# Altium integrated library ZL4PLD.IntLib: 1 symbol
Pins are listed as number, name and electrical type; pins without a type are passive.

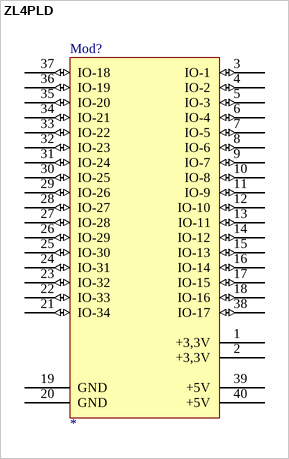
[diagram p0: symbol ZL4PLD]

## ZL4PLD
designator Mod?
www.btc.pl
footprint ZL4PLD
pins: 1 +3,3V (power), 2 +3,3V (power), 3 IO-1 (io), 4 IO-2 (io), 5 IO-3 (io), 6 IO-4 (io), 7 IO-5 (io), 8 IO-6 (io), 9 IO-7 (io), 10 IO-8 (io), 11 IO-9 (io), 12 IO-10 (io), 13 IO-11 (io), 14 IO-12 (io), 15 IO-13 (io), 16 IO-14 (io), 17 IO-15 (io), 18 IO-16 (io), 19 GND (power), 20 GND (power), 21 IO-34 (io), 22 IO-33 (io), 23 IO-32 (io), 24 IO-31 (io), 25 IO-30 (io), 26 IO-29 (io), 27 IO-28 (io), 28 IO-27 (io), 29 IO-26 (io), 30 IO-25 (io), 31 IO-24 (io), 32 IO-23 (io), 33 IO-22 (io), 34 IO-21 (io), 35 IO-20 (io), 36 IO-19 (io), 37 IO-18 (io), 38 IO-17 (io), 39 +5V (power), 40 +5V (power)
